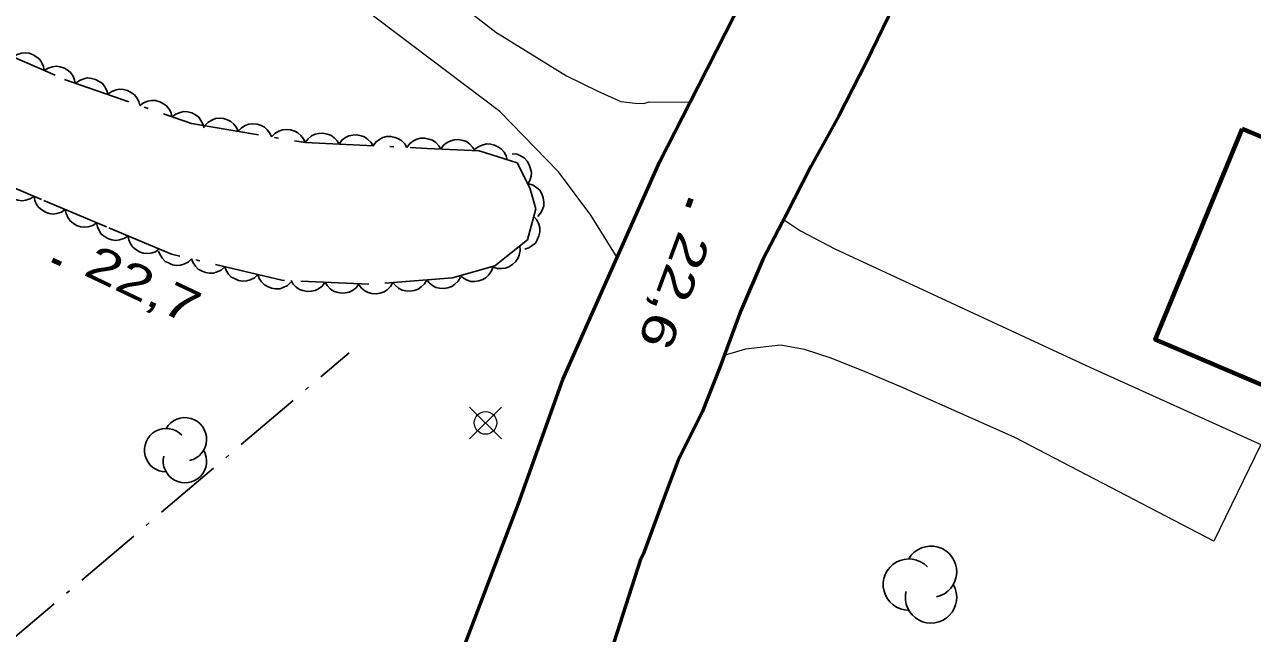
# Model space of a CAD drawing. Extents: x 356765 to 358572, y 5103174 to 5104650.
# Drawn here: x 357232 to 357286.2, y 5103992.9 to 5104019.8 of the extents above; entities that cross this region are included whole.
import ezdxf

# ---------------------------------------------------------------- set-up
doc = ezdxf.new("R2010")
doc.units = 0
doc.header["$LTSCALE"] = 0.6
doc.linetypes.add('DOT_DASHED', pattern=[7.7, 5, -1.2, 0.3, -1.2])
for name, color, linetype, lineweight in [('19', 7, 'Continuous', 13), ('21', 7, 'Continuous', 53), ('3', 7, 'Continuous', 140), ('31', 7, 'Continuous', 70), ('36', 7, 'Continuous', 13), ('41', 7, 'DOT_DASHED', 25), ('44', 7, 'Continuous', 25)]:
    doc.layers.add(name, color=color, linetype=linetype, lineweight=lineweight)

msp = doc.modelspace()

# ---------------------------------------------------------------- linework, layer by layer
at = {"layer": '19'}
for points in [[(357258.19, 5104009.55), (357257.02, 5104011.41), (357255.59, 5104013.33), (357253, 5104015.99), (357242.14, 5104024.2), (357243.93, 5104026.26), (357249.05, 5104022.43), (357252.82, 5104019.49), (357255.94, 5104017.56), (357257.33, 5104016.89), (357258.34, 5104016.43), (357258.98, 5104016.36), (357259.36, 5104016.34), (357259.59, 5104016.41), (357261.4, 5104016.4)], [(357265.53, 5104011.22), (357266.28, 5104010.72), (357267.8, 5104009.92), (357279.06, 5104004.7), (357286.61, 5104001.28), (357284.54, 5103997.01), (357275.74, 5104001.59), (357270.81, 5104003.79), (357269.28, 5104004.44), (357267.63, 5104005.09), (357266.46, 5104005.48), (357265.4, 5104005.67), (357263.85, 5104005.5), (357262.91, 5104005.22)]]:
    msp.add_lwpolyline(points, dxfattribs=at)
at = {"layer": '21'}
for points in [[(357235, 5103902.34), (357236.8, 5103914.18), (357238.16, 5103922.98), (357240.84, 5103943.53), (357241.93, 5103951.26), (357243.11, 5103959.18), (357244.3, 5103966.44), (357246.54, 5103976.17), (357248.33, 5103983.55), (357249.72, 5103987.87), (357253.83, 5103998.68), (357255.78, 5104004.15), (357260.07, 5104013.78), (357261.4, 5104016.4), (357265.26, 5104023.99), (357269.42, 5104032.09), (357274.09, 5104040.95), (357277.93, 5104048.22), (357278.25, 5104048.83), (357280.69, 5104053.09)], [(357270.4, 5104020.67), (357269.19, 5104018.19), (357267.98, 5104015.8), (357266.75, 5104013.59), (357265.64, 5104011.43), (357264.61, 5104009.46), (357263.63, 5104007.16), (357262.71, 5104004.69), (357261.94, 5104002.71), (357260.88, 5104000.59), (357260.21, 5103998.83), (357259.33, 5103996.43), (357259.22, 5103996.21), (357256.71, 5103988.42)]]:
    msp.add_lwpolyline(points, dxfattribs=at)
at = {"layer": '3'}
for p, q in [((357261.44, 5104012.14), (357261.3, 5104011.77)), ((357233.25, 5104009.44), (357233.61, 5104009.27))]:
    msp.add_line(p, q, dxfattribs=at)
at = {"layer": '31'}
msp.add_lwpolyline([(357285.78, 5104015.23), (357295.38, 5104011.26), (357292.54, 5104004.34), (357294.39, 5104003.55), (357293.39, 5104001.05), (357281.95, 5104005.92), (357285.78, 5104015.23)], close=True, dxfattribs=at)
at = {"layer": '36'}
for p, q in [((357253.07, 5104001.53), (357251.66, 5104002.94)), ((357251.66, 5104001.53), (357253.07, 5104002.94))]:
    msp.add_line(p, q, dxfattribs=at)
msp.add_circle((357252.3668, 5104002.2374), 0.5, dxfattribs=at)
at = {"layer": '41'}
msp.add_line((357192.32, 5103959.37), (357246.34, 5104005.33), dxfattribs=at)
at = {"layer": '44', "linetype": 'DOT_DASHED'}
msp.add_lwpolyline([(357230.61, 5104018.78), (357233.78, 5104017.41), (357239.38, 5104015.46), (357244.42, 5104014.62), (357249.79, 5104014.36), (357252.09, 5104014.26), (357253.76, 5104013.72), (357254.33, 5104012.62), (357254.59, 5104011.69), (357254.22, 5104010.33), (357252.78, 5104009.17), (357250.91, 5104008.65), (357247.21, 5104008.36), (357243.37, 5104008.54), (357238.5, 5104009.69), (357235.63, 5104010.89), (357232.76, 5104012.1), (357226.73, 5104014.68)], dxfattribs=at)
at = {"layer": '44'}
for points in [[(357231.5, 5104018.39), (357231.68, 5104018.51), (357231.88, 5104018.56), (357232.04, 5104018.58), (357232.21, 5104018.56), (357232.39, 5104018.5), (357232.55, 5104018.39), (357232.68, 5104018.29), (357232.77, 5104018.14), (357232.85, 5104017.98), (357232.88, 5104017.8)], [(357232.88, 5104017.8), (357233.06, 5104017.91), (357233.25, 5104017.97), (357233.42, 5104017.99), (357233.59, 5104017.96), (357233.77, 5104017.9), (357233.93, 5104017.8), (357234.05, 5104017.7), (357234.15, 5104017.55), (357234.22, 5104017.38), (357234.26, 5104017.2)], [(357234.27, 5104017.24), (357234.44, 5104017.36), (357234.63, 5104017.43), (357234.79, 5104017.47), (357234.97, 5104017.45), (357235.15, 5104017.41), (357235.31, 5104017.32), (357235.45, 5104017.22), (357235.56, 5104017.08), (357235.64, 5104016.92), (357235.69, 5104016.75)], [(357235.69, 5104016.75), (357235.86, 5104016.87), (357236.05, 5104016.94), (357236.21, 5104016.97), (357236.38, 5104016.96), (357236.56, 5104016.92), (357236.73, 5104016.82), (357236.86, 5104016.73), (357236.97, 5104016.59), (357237.06, 5104016.43), (357237.1, 5104016.25)], [(357237.1, 5104016.25), (357237.27, 5104016.38), (357237.46, 5104016.45), (357237.63, 5104016.48), (357237.8, 5104016.47), (357237.98, 5104016.42), (357238.15, 5104016.33), (357238.28, 5104016.24), (357238.39, 5104016.1), (357238.48, 5104015.93), (357238.52, 5104015.76)], [(357238.52, 5104015.76), (357238.69, 5104015.88), (357238.88, 5104015.95), (357239.04, 5104015.99), (357239.22, 5104015.97), (357239.4, 5104015.93), (357239.56, 5104015.84), (357239.7, 5104015.74), (357239.8, 5104015.6), (357239.89, 5104015.44), (357239.94, 5104015.27)], [(357239.96, 5104015.36), (357240.11, 5104015.51), (357240.28, 5104015.61), (357240.44, 5104015.68), (357240.61, 5104015.69), (357240.8, 5104015.68), (357240.98, 5104015.62), (357241.12, 5104015.55), (357241.25, 5104015.43), (357241.37, 5104015.28), (357241.44, 5104015.12)], [(357241.44, 5104015.12), (357241.59, 5104015.27), (357241.76, 5104015.37), (357241.92, 5104015.43), (357242.09, 5104015.45), (357242.28, 5104015.43), (357242.46, 5104015.37), (357242.6, 5104015.3), (357242.73, 5104015.18), (357242.85, 5104015.03), (357242.92, 5104014.87)], [(357242.92, 5104014.87), (357243.07, 5104015.02), (357243.24, 5104015.12), (357243.4, 5104015.18), (357243.57, 5104015.2), (357243.76, 5104015.18), (357243.94, 5104015.12), (357244.08, 5104015.05), (357244.21, 5104014.93), (357244.33, 5104014.79), (357244.4, 5104014.62)], [(357244.4, 5104014.62), (357244.53, 5104014.79), (357244.69, 5104014.91), (357244.84, 5104014.99), (357245.01, 5104015.02), (357245.19, 5104015.03), (357245.38, 5104014.99), (357245.53, 5104014.94), (357245.68, 5104014.83), (357245.81, 5104014.7), (357245.9, 5104014.55)], [(357245.9, 5104014.55), (357246.02, 5104014.72), (357246.19, 5104014.84), (357246.33, 5104014.91), (357246.51, 5104014.95), (357246.69, 5104014.96), (357246.88, 5104014.92), (357247.03, 5104014.87), (357247.17, 5104014.76), (357247.3, 5104014.63), (357247.4, 5104014.48)], [(357247.4, 5104014.48), (357247.52, 5104014.64), (357247.69, 5104014.76), (357247.83, 5104014.84), (357248, 5104014.88), (357248.19, 5104014.89), (357248.38, 5104014.84), (357248.53, 5104014.79), (357248.67, 5104014.69), (357248.8, 5104014.56), (357248.9, 5104014.4)], [(357248.9, 5104014.4), (357249.02, 5104014.57), (357249.19, 5104014.69), (357249.33, 5104014.77), (357249.5, 5104014.81), (357249.69, 5104014.81), (357249.87, 5104014.77), (357250.03, 5104014.72), (357250.17, 5104014.62), (357250.3, 5104014.48), (357250.39, 5104014.33)], [(357250.39, 5104014.33), (357250.52, 5104014.5), (357250.68, 5104014.62), (357250.83, 5104014.7), (357251, 5104014.74), (357251.18, 5104014.75), (357251.37, 5104014.71), (357251.53, 5104014.66), (357251.67, 5104014.55), (357251.8, 5104014.42), (357251.89, 5104014.27)], [(357251.9, 5104014.32), (357252.07, 5104014.45), (357252.26, 5104014.52), (357252.42, 5104014.56), (357252.59, 5104014.55), (357252.77, 5104014.51), (357252.94, 5104014.42), (357253.08, 5104014.33), (357253.19, 5104014.19), (357253.28, 5104014.03), (357253.33, 5104013.86)], [(357253.55, 5104014.12), (357253.76, 5104014.1), (357253.95, 5104014.02), (357254.09, 5104013.93), (357254.21, 5104013.8), (357254.3, 5104013.64), (357254.36, 5104013.46), (357254.4, 5104013.3), (357254.38, 5104013.13), (357254.33, 5104012.95), (357254.24, 5104012.79)], [(357232.43, 5104012.24), (357232.25, 5104012.13), (357232.06, 5104012.07), (357231.9, 5104012.05), (357231.72, 5104012.07), (357231.55, 5104012.13), (357231.38, 5104012.24), (357231.26, 5104012.34), (357231.16, 5104012.49), (357231.09, 5104012.65), (357231.05, 5104012.83)], [(357254.28, 5104012.8), (357254.48, 5104012.74), (357254.64, 5104012.62), (357254.76, 5104012.51), (357254.85, 5104012.36), (357254.92, 5104012.18), (357254.94, 5104011.99), (357254.94, 5104011.83), (357254.88, 5104011.66), (357254.8, 5104011.5), (357254.68, 5104011.36)], [(357233.81, 5104011.66), (357233.64, 5104011.54), (357233.44, 5104011.49), (357233.28, 5104011.46), (357233.1, 5104011.49), (357232.93, 5104011.54), (357232.77, 5104011.65), (357232.64, 5104011.75), (357232.54, 5104011.89), (357232.46, 5104012.06), (357232.43, 5104012.24)], [(357235.19, 5104011.07), (357235.02, 5104010.96), (357234.82, 5104010.9), (357234.66, 5104010.88), (357234.49, 5104010.9), (357234.31, 5104010.96), (357234.15, 5104011.06), (357234.02, 5104011.16), (357233.92, 5104011.31), (357233.85, 5104011.48), (357233.81, 5104011.66)], [(357236.58, 5104010.49), (357236.4, 5104010.38), (357236.21, 5104010.32), (357236.04, 5104010.3), (357235.87, 5104010.32), (357235.69, 5104010.38), (357235.53, 5104010.48), (357235.4, 5104010.58), (357235.31, 5104010.73), (357235.23, 5104010.9), (357235.19, 5104011.07)], [(357254.5, 5104011.36), (357254.64, 5104011.2), (357254.72, 5104011.01), (357254.76, 5104010.86), (357254.76, 5104010.68), (357254.73, 5104010.5), (357254.65, 5104010.32), (357254.57, 5104010.18), (357254.43, 5104010.07), (357254.28, 5104009.97), (357254.11, 5104009.91)], [(357237.96, 5104009.92), (357237.79, 5104009.8), (357237.59, 5104009.74), (357237.43, 5104009.72), (357237.25, 5104009.74), (357237.08, 5104009.8), (357236.92, 5104009.9), (357236.79, 5104010), (357236.69, 5104010.15), (357236.61, 5104010.32), (357236.58, 5104010.49)], [(357253.88, 5104010.06), (357253.9, 5104009.85), (357253.86, 5104009.65), (357253.8, 5104009.5), (357253.7, 5104009.35), (357253.56, 5104009.23), (357253.4, 5104009.13), (357253.25, 5104009.07), (357253.07, 5104009.05), (357252.89, 5104009.06), (357252.71, 5104009.12)], [(357239.39, 5104009.48), (357239.24, 5104009.34), (357239.05, 5104009.25), (357238.9, 5104009.2), (357238.72, 5104009.19), (357238.54, 5104009.22), (357238.36, 5104009.3), (357238.22, 5104009.37), (357238.1, 5104009.5), (357238, 5104009.66), (357237.93, 5104009.82)], [(357240.85, 5104009.13), (357240.7, 5104008.99), (357240.51, 5104008.91), (357240.36, 5104008.85), (357240.18, 5104008.85), (357240, 5104008.88), (357239.82, 5104008.95), (357239.68, 5104009.03), (357239.56, 5104009.16), (357239.46, 5104009.31), (357239.39, 5104009.48)], [(357242.31, 5104008.79), (357242.16, 5104008.65), (357241.97, 5104008.56), (357241.82, 5104008.51), (357241.64, 5104008.5), (357241.46, 5104008.53), (357241.28, 5104008.61), (357241.14, 5104008.68), (357241.02, 5104008.81), (357240.92, 5104008.97), (357240.85, 5104009.13)], [(357252.7, 5104009.15), (357252.63, 5104008.95), (357252.51, 5104008.78), (357252.4, 5104008.66), (357252.25, 5104008.57), (357252.08, 5104008.51), (357251.89, 5104008.49), (357251.72, 5104008.49), (357251.56, 5104008.54), (357251.39, 5104008.63), (357251.25, 5104008.75)], [(357243.77, 5104008.45), (357243.62, 5104008.3), (357243.43, 5104008.22), (357243.28, 5104008.16), (357243.1, 5104008.16), (357242.92, 5104008.19), (357242.74, 5104008.26), (357242.6, 5104008.34), (357242.48, 5104008.47), (357242.37, 5104008.62), (357242.31, 5104008.79)], [(357245.28, 5104008.45), (357245.15, 5104008.28), (357244.99, 5104008.16), (357244.85, 5104008.08), (357244.67, 5104008.05), (357244.49, 5104008.04), (357244.3, 5104008.08), (357244.15, 5104008.13), (357244.01, 5104008.23), (357243.88, 5104008.37), (357243.78, 5104008.52)], [(357246.78, 5104008.38), (357246.65, 5104008.21), (357246.49, 5104008.09), (357246.34, 5104008.01), (357246.17, 5104007.98), (357245.99, 5104007.97), (357245.8, 5104008.01), (357245.65, 5104008.06), (357245.5, 5104008.16), (357245.37, 5104008.3), (357245.28, 5104008.45)], [(357248.27, 5104008.44), (357248.17, 5104008.26), (357248.02, 5104008.12), (357247.89, 5104008.03), (357247.72, 5104007.97), (357247.54, 5104007.94), (357247.35, 5104007.95), (357247.19, 5104007.99), (357247.04, 5104008.07), (357246.89, 5104008.19), (357246.78, 5104008.33)], [(357249.77, 5104008.56), (357249.67, 5104008.38), (357249.52, 5104008.24), (357249.39, 5104008.14), (357249.22, 5104008.08), (357249.04, 5104008.05), (357248.85, 5104008.07), (357248.69, 5104008.1), (357248.53, 5104008.19), (357248.39, 5104008.3), (357248.27, 5104008.44)], [(357251.27, 5104008.68), (357251.16, 5104008.5), (357251.01, 5104008.36), (357250.88, 5104008.26), (357250.71, 5104008.2), (357250.53, 5104008.17), (357250.34, 5104008.19), (357250.18, 5104008.22), (357250.03, 5104008.3), (357249.88, 5104008.42), (357249.77, 5104008.56)]]:
    msp.add_lwpolyline(points, dxfattribs=at)
for centre, radius, start, end in [((357239.0912, 5104001.5121), 0.9606, 282.26917, 149.72626), ((357238.2651, 5104001.0318), 0.9606, 44.11537, 269.80396), ((357239.0912, 5104000.5515), 0.9606, 166.93686, 29.62122), ((357272.0439, 5103995.663), 1.1345, 282.26917, 149.72626), ((357271.0682, 5103995.0958), 1.1345, 44.11537, 269.80396), ((357272.0439, 5103994.5285), 1.1345, 166.93686, 29.62122)]:
    msp.add_arc(centre, radius, start, end, dxfattribs=at)

# ---------------------------------------------------------------- texts
at = {"layer": '3', "width": 1.35}
for s, rotation, p in [('22,6   ', 249.666, (357260.92, 5104010.79)), ('22,7   ', 334.619, (357234.55, 5104008.8))]:
    msp.add_text(s, height=1.5, rotation=rotation, dxfattribs=at).set_placement(p)

doc.saveas('drawing.dxf')
